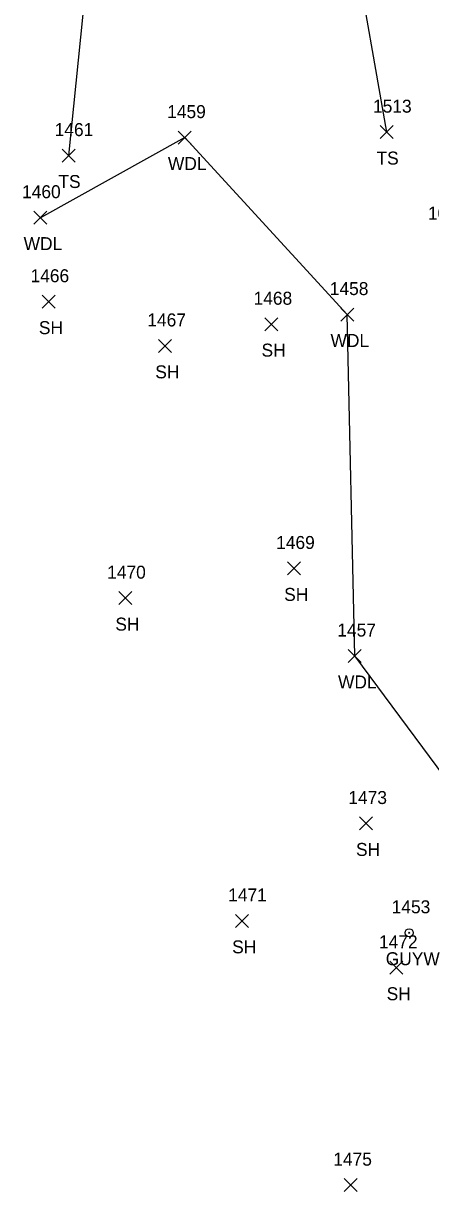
# Model space of a CAD drawing. Extents: x 462930 to 463548, y 29607 to 30453.
# Drawn here: x 463308.8 to 463327.9, y 30004.8 to 30059.7 of the extents above; entities that cross this region are included whole.
import ezdxf

# ---------------------------------------------------------------- set-up
doc = ezdxf.new("R2010")
doc.units = 0
for name, color, linetype in [('L_A', 7, 'Continuous'), ('L_I', 7, 'Continuous'), ('L_TIC', 7, 'Continuous'), ('LAWA', 7, 'Continuous'), ('LELB', 7, 'Continuous'), ('U_A', 7, 'Continuous'), ('U_I', 7, 'Continuous'), ('UPGW', 7, 'Continuous')]:
    doc.layers.add(name, color=color, linetype=linetype)

msp = doc.modelspace()

# ---------------------------------------------------------------- linework, layer by layer
at = {"layer": 'L_TIC'}
for points in [[(463316.064, 30054.003), (463316.674, 30054.613)], [(463316.674, 30054.003), (463316.064, 30054.613)], [(463325.55, 30054.259), (463326.16, 30054.869)], [(463326.16, 30054.259), (463325.55, 30054.869)], [(463310.622, 30053.159), (463311.232, 30053.769)], [(463311.232, 30053.159), (463310.622, 30053.769)], [(463309.292, 30050.242), (463309.902, 30050.852)], [(463309.902, 30050.242), (463309.292, 30050.852)], [(463309.68, 30046.296), (463310.29, 30046.906)], [(463310.29, 30046.296), (463309.68, 30046.906)], [(463323.694, 30045.693), (463324.304, 30046.303)], [(463324.304, 30045.693), (463323.694, 30046.303)], [(463320.131, 30045.24), (463320.741, 30045.85)], [(463320.741, 30045.24), (463320.131, 30045.85)], [(463315.144, 30044.221), (463315.754, 30044.831)], [(463315.754, 30044.221), (463315.144, 30044.831)], [(463321.193, 30033.769), (463321.803, 30034.379)], [(463321.803, 30033.769), (463321.193, 30034.379)], [(463313.271, 30032.374), (463313.881, 30032.984)], [(463313.881, 30032.374), (463313.271, 30032.984)], [(463324.047, 30029.658), (463324.657, 30030.268)], [(463324.657, 30029.658), (463324.047, 30030.268)], [(463324.565, 30021.792), (463325.175, 30022.402)], [(463325.175, 30021.792), (463324.565, 30022.402)], [(463318.751, 30017.218), (463319.361, 30017.828)], [(463319.361, 30017.218), (463318.751, 30017.828)], [(463326.004, 30015.016), (463326.614, 30015.626)], [(463326.614, 30015.016), (463326.004, 30015.626)], [(463323.858, 30004.808), (463324.468, 30005.418)], [(463324.468, 30004.808), (463323.858, 30005.418)]]:
    msp.add_lwpolyline(points, dxfattribs=at)
at = {"layer": 'LAWA'}
msp.add_lwpolyline([(463330.432, 30016.711), (463328.933, 30023.785), (463324.352, 30029.963), (463323.999, 30045.998), (463316.369, 30054.308), (463309.597, 30050.547)], dxfattribs=at)
at = {"layer": 'LELB'}
for points in [[(463310.927, 30053.464), (463312.187, 30065.834), (463313.324, 30072.303), (463313.866, 30075.077), (463316.627, 30080.583)], [(463325.855, 30054.564), (463324.311, 30063.409)]]:
    msp.add_lwpolyline(points, dxfattribs=at)
at = {"layer": 'UPGW'}
for radius in [0.191, 0.0254]:
    msp.add_circle((463326.903, 30016.965), radius, dxfattribs=at)

# ---------------------------------------------------------------- texts
at = {"layer": 'L_A'}
for s, p in [('WDL', (463315.582, 30052.784)), ('TS', (463325.37, 30053.04)), ('TS', (463310.442, 30051.94)), ('WDL', (463308.81, 30049.023)), ('SH', (463309.524, 30045.077)), ('WDL', (463323.212, 30044.474)), ('SH', (463319.975, 30044.021)), ('SH', (463314.988, 30043.002)), ('SH', (463321.037, 30032.55)), ('SH', (463313.115, 30031.155)), ('WDL', (463323.565, 30028.439)), ('SH', (463324.409, 30020.573)), ('SH', (463318.595, 30015.999)), ('SH', (463325.848, 30013.797))]:
    msp.add_text(s, height=0.6096, dxfattribs=at).set_placement(p)
at = {"layer": 'L_I'}
for s, p in [('1513', (463325.207, 30055.478)), ('1459', (463315.546, 30055.222)), ('1461', (463310.265, 30054.378)), ('1460', (463308.735, 30051.461)), ('1037', (463327.786, 30050.454)), ('1466', (463309.133, 30047.515)), ('1458', (463323.178, 30046.912)), ('1468', (463319.601, 30046.459)), ('1467', (463314.614, 30045.44)), ('1469', (463320.66, 30034.988)), ('1470', (463312.729, 30033.593)), ('1457', (463323.531, 30030.877)), ('1473', (463324.049, 30023.011)), ('1471', (463318.408, 30018.437)), ('1472', (463325.488, 30016.235)), ('1475', (463323.342, 30006.027))]:
    msp.add_text(s, height=0.6096, dxfattribs=at).set_placement(p)
at = {"layer": 'U_A'}
msp.add_text('GUYW', height=0.6096, dxfattribs=at).set_placement((463325.804, 30015.441))
at = {"layer": 'U_I'}
msp.add_text('1453', height=0.6096, dxfattribs=at).set_placement((463326.082, 30017.879))

doc.saveas('drawing.dxf')
